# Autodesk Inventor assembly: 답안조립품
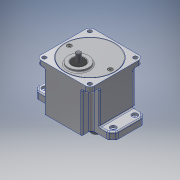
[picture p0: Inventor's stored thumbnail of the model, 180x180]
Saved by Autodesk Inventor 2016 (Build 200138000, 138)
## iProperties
Created: 2017-01
Part Number: 답안조립품
Material: 일반
Document SubType Name: Assembly
Designer: Owner
Author: Owner
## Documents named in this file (10)
- H:\470111V1017\답안조립품.iam
- H:\470111V1017\본체.ipt
- H:\470111V1017\메인축.ipt
- H:\470111V1017\베어링 608.ipt
- H:\470111V1017\베어링 6003.ipt
- H:\470111V1017\볼트 M4 x 10.ipt
- H:\470111V1017\서브축.ipt
- H:\470111V1017\오일실 8 22 7.ipt
- H:\470111V1017\오일실 17 32 8.ipt
- H:\470111V1017\커버.ipt
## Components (2 placed, 1 different names)
1. ISO 4762 M4 x 10:1
2. ISO 4762 M4 x 10:2
